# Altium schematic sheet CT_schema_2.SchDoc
size 214 x 189 mm
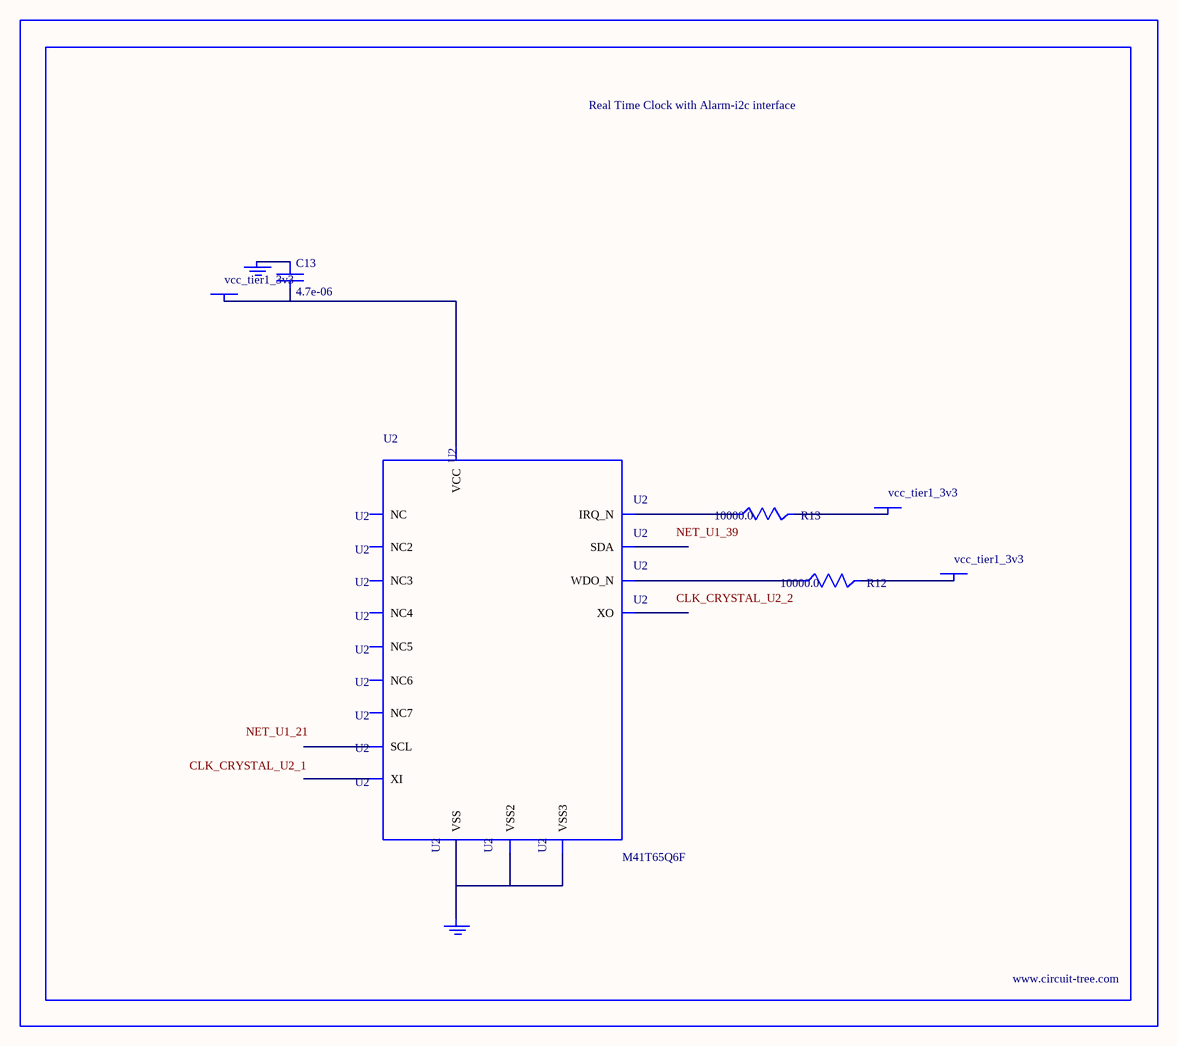
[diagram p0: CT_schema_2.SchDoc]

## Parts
BORDER1  (no value)
C13  4.7e-06  [C0805]
GND_INSTANCE_1_0  (no value)
GND_INSTANCE_1_1  (no value)
POWER_INSTANCE_1_0  vcc_tier1_3v3
POWER_INSTANCE_1_1  vcc_tier1_3v3
POWER_INSTANCE_1_2  vcc_tier1_3v3
R12  10000.0  [R0603]
R13  10000.0  [R0603]
U2  M41T65Q6F  [M41T65_QFN-16]

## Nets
NetC13_1: C13.1 GND_INSTANCE_1_0.0(GND)
NetC13_2: C13.2 POWER_INSTANCE_1_2.0(PWR) U2.14(VCC)
NetGND_INSTANCE_1_1_0: GND_INSTANCE_1_1.0(GND) U2.3(VSS) U2.5(VSS2) U2.17(VSS3)
NetPOWER_INSTANCE_1_0_0: POWER_INSTANCE_1_0.0(PWR) R12.2
NetPOWER_INSTANCE_1_1_0: POWER_INSTANCE_1_1.0(PWR) R13.2
NetR12_1: R12.1 U2.4(WDO_N)
NetR13_1: R13.1 U2.11(IRQ_N)

Not connected (* = marked no-connect by the designer): U2 1(XI) 2(XO) 6(NC) 7(NC2) 8(NC3) 9(SDA) 10(SCL) 12(NC4) 13(NC5) 15(NC6) 16(NC7)

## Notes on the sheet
- Labels drawn without touching a wire or pin: CLK_CRYSTAL_U2_1, CLK_CRYSTAL_U2_2, NET_U1_21, NET_U1_39

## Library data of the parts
BORDER1 = BORDER_PAGE1
C13 = C0805C475K4RACTU
GND_INSTANCE_1_0 GND_INSTANCE_1_1 = GND
POWER_INSTANCE_1_0-POWER_INSTANCE_1_2 = PWR
R12 R13 = RC0603JR-0710KL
